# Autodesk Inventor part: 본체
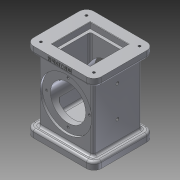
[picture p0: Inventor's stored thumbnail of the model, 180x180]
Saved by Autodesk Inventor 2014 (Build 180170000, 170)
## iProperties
Created: 2017-08
Part Number: 본체
Material: 알루미늄 6061
Document SubType Name: Modeling
Designer: 601-14
Density: 2.71 g/cm^3
Appearance: 알루미늄 - 평지
Mass: 872.531 g
Surface Area: 642.848 cm^2
Volume: 321.967 cm^3
Author: 601-14
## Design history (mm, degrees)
sketch "스케치1"
  geometry: L1 (46, 41)-(-46, 41); L2 (-46, 41)-(-46, -41); L3 (-46, -41)-(46, -41); L4 (46, -41)-(46, 41); L5 (46, 41)-(-46, -41); L6 (-46, 41)-(46, -41); 1 further point
  constraints: 12 end point, 2 midpoint, 2 parallel, 1 horizontal, 1 perpendicular
  dimensions: "d0" = 82 distance of L3.end L1.start; "d1" = 92 distance between parallel lines of L4 L2
extrude "돌출1" new body sketch "스케치1" distance "d2" = 10; taper "d3" = 0 deg
sketch "스케치2"
  geometry: L1 (37, 33)-(-37, 33); L2 (-37, 33)-(-37, -33); L3 (-37, -33)-(37, -33); L4 (37, -33)-(37, 33); L5 (37, 33)-(-37, -33); L6 (-37, 33)-(37, -33); 1 further point
  constraints: 12 end point, 2 midpoint, 2 parallel, 1 horizontal, 1 perpendicular
  dimensions: "d4" = 74 distance between parallel lines of L4 L2; "d5" = 66 distance between parallel lines of L3 L1
extrude "돌출2" join sketch "스케치2" distance "d6" = 88; taper "d7" = 0 deg
sketch "스케치3"
  geometry: L1 (46, 41)-(-46, 41); L2 (-46, 41)-(-46, -41); L3 (-46, -41)-(46, -41); L4 (46, -41)-(46, 41); L5 (46, 41)-(-46, -41); L6 (-46, 41)-(46, -41); 1 further point
  constraints: 12 end point, 2 midpoint, 2 parallel, 1 horizontal, 1 perpendicular
  dimensions: "d8" = 92 distance between parallel lines of L4 L2; "d9" = 82 distance between parallel lines of L3 L1
extrude "돌출3" join sketch "스케치3" distance "d10" = 10; taper "d11" = 0 deg
sketch "스케치5"
  geometry: L1 (-9, -10)-(83, -10) reference; C1 r 35 at (37, 44); 1 further point
  constraints: 1 centre point
  dimensions: "d12" = 70 diameter of C1; "d13" = 54 distance from line of L1 C1.centre
extrude "돌출4" cut sketch "스케치5" distance "d14" = 3; taper "d15" = 0 deg
sketch "스케치6"
  geometry: L1 (83, 10)-(-9, 10) reference; C1 r 35 at (37, -44); 1 further point
  constraints: 1 centre point
  dimensions: "d16" = 70 diameter of C1; "d17" = 54 distance from line of L1 C1.centre
extrude "돌출5" cut sketch "스케치6" distance "d18" = 3; taper "d19" = 0 deg
sketch "스케치7"
  geometry: C1 r 35 at (0, 0) reference; C2 r 24 at (0, 0); 1 further point
  constraints: 1 centre point, 1 coincident
  dimensions: "d20" = 48 diameter of C2
extrude "돌출6" cut sketch "스케치7" distance "d21" = 68; taper "d22" = 0 deg
sketch "스케치8" dims "d23" = 58
  geometry: L1 (0, 0)-(0, 54.477); C1 r 35 at (0, 0) reference; 2 further points
  constraints: 2 end point, 1 coincident, 1 point on line, 1 vertical, 1 vertical alignment, 2 other
hole "구멍1" sketch "스케치8" at (0, 29) diameter "d24" = 3.242; stored, may be unused: countersink angle "d28" = 90 deg, drill point angle "d30" = 118 deg; dims "d25" = 4, "d26" = 4, "d27" = 2, "d29" = 6
node "작업 평면1"
sketch "스케치9"
  geometry: L1 (26, 26)-(-26, 26); L2 (-26, 26)-(-26, -26); L3 (-26, -26)-(26, -26); L4 (26, -26)-(26, 26); L5 (26, 26)-(-26, -26); L6 (-26, 26)-(26, -26); 1 further point
  constraints: 12 end point, 2 midpoint, 2 parallel, 1 horizontal, 1 perpendicular
  dimensions: "d34" = 52 distance between parallel lines of L3 L1; "d35" = 52 distance between parallel lines of L4 L2
extrude "돌출7" cut sketch "스케치9" distance "d36" = 8; taper "d37" = 0 deg
sketch "스케치10"
  geometry: L1 (24, 24)-(-24, 24); L2 (-24, 24)-(-24, -24); L3 (-24, -24)-(24, -24); L4 (24, -24)-(24, 24); L5 (24, 24)-(-24, -24); L6 (-24, 24)-(24, -24); 1 further point
  constraints: 12 end point, 2 midpoint, 2 parallel, 1 horizontal, 1 perpendicular
  dimensions: "d38" = 48 distance between parallel lines of L3 L1; "d39" = 48 distance between parallel lines of L2 L4
extrude "돌출8" cut sketch "스케치10" distance "d40" = 16; taper "d41" = 0 deg
sketch "스케치11"
  geometry: L1 (22, 22)-(-22, 22); L2 (-22, 22)-(-22, -22); L3 (-22, -22)-(22, -22); L4 (22, -22)-(22, 22); L5 (22, 22)-(-22, -22); L6 (-22, 22)-(22, -22); 1 further point
  constraints: 12 end point, 2 midpoint, 2 parallel, 1 horizontal, 1 perpendicular
  dimensions: "d42" = 44 distance between parallel lines of L3 L1; "d43" = 44 distance between parallel lines of L2 L4
extrude "돌출9" cut sketch "스케치11" distance "d44" = 74; taper "d45" = 0 deg
sketch "스케치12"
  geometry: L1 (0, 66)-(0, 0) reference; L2 (-88, 0)-(-88, 66) reference; L3 (-88, 33)-(0, 33); L4 (10, -8)-(10, 74) reference; 3 further points
  constraints: 2 end point, 2 midpoint, 2 point on line
  dimensions: "d46" = 38 distance from line of L4 point (-28, 33); "d47" = 42 distance of point (-28, 33) point (-70, 33)
hole "구멍2" sketch "스케치12" at (-28, 33), (-70, 33) diameter "d48" = 4.134; stored, may be unused: countersink angle "d52" = 90 deg, drill point angle "d54" = 118 deg; dims "d49" = 20, "d50" = 4, "d51" = 2, "d53" = 20
sketch "스케치13"
  geometry: L1 (36, 31)-(-36, 31); L2 (-36, 31)-(-36, -31); L3 (-36, -31)-(36, -31); L4 (36, -31)-(36, 31); L5 (36, 31)-(-36, -31); L6 (-36, 31)-(36, -31); 5 further points
  constraints: 12 end point, 4 coincident, 2 midpoint, 2 parallel, 1 horizontal, 1 perpendicular
  dimensions: "d55" = 72 distance between parallel lines of L4 L2; "d56" = 62 distance between parallel lines of L3 L1
hole "구멍3" sketch "스케치13" at (-36, 31), (-36, -31), (36, 31), (36, -31) diameter "d57" = 3.242; stored, may be unused: countersink angle "d61" = 90 deg, drill point angle "d63" = 118 deg; dims "d58" = 4, "d59" = 4, "d60" = 2, "d62" = 6
node "작업 평면2"
sketch "스케치14"
  geometry: L1 (0, 10)-(92, 10) reference; L2 (0, 0)-(0, 10) reference; 2 further points
  constraints: 1 other
  dimensions: "d65" = 4 distance from line of point (46, 6) L1; "d66" = 46 distance from line of point (46, 6) L2
feature "엠보싱1" sketch "스케치14" dims "d0" = 82, "d1" = 92, "d67" = 0.5, "d68" = 0
fillet "모깎기1" dims "d69" = 10
fillet "모깎기2" dims "d70" = 3
fillet "모깎기3" dims "d71" = 3
fillet "모깎기4" dims "d72" = 3
fillet "모깎기5" dims "d73" = 3
fillet "모깎기6" dims "d74" = 3
fillet "모깎기7" dims "d75" = 3
fillet "모깎기8" dims "d76" = 3
chamfer "모따기2" distance "d80" = 0.5; stored, may be unused: second distance "d81" = 2, angle "d82" = 45 deg
node "솔리드1"
pattern_circular "원형 패턴1" dims angle "d32" = 360 deg
mirror "대칭1"
mirror "대칭2"
